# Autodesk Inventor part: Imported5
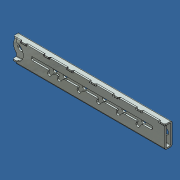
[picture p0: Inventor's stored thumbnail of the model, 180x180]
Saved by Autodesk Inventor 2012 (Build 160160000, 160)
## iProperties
Created: 2016-01
Part Number: Imported5
Material: Steel
Document SubType Name: Modeling
Designer: Admin
Density: 7.85 g/cm^3
Mass: 183.43 g
Surface Area: 256.265 cm^2
Volume: 23.3669 cm^3
Author: Admin
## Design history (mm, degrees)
feature "Base1"
sketch "Sketch1"
  geometry: L1 (147.702, 10.784)-(148.047, 11.276) reference; L2 (147.228, 12.85)-(145.697, 12.85) reference; L3 (138.598, 7.916)-(139.963, 9.865) reference; L4 (134.502, 10.784)-(134.847, 11.276) reference; L5 (134.028, 12.85)-(132.497, 12.85) reference; L6 (125.398, 7.916)-(126.763, 9.865) reference; L7 (121.302, 10.784)-(121.647, 11.276) reference; L8 (120.828, 12.85)-(119.297, 12.85) reference; L9 (112.198, 7.916)-(113.563, 9.865) reference; L10 (108.102, 10.784)-(108.447, 11.276) reference; L11 (107.628, 12.85)-(106.097, 12.85) reference; L12 (98.998, 7.916)-(100.363, 9.865) reference; L13 (94.902, 10.784)-(95.247, 11.276) reference; L14 (94.428, 12.85)-(92.897, 12.85) reference; L15 (85.798, 7.916)-(87.163, 9.865) reference; L16 (81.702, 10.784)-(82.047, 11.276) reference; L17 (81.228, 12.85)-(79.697, 12.85) reference; L18 (72.598, 7.916)-(73.963, 9.865) reference; L19 (68.502, 10.784)-(68.847, 11.276) reference; L20 (68.028, 12.85)-(66.497, 12.85) reference; L21 (59.398, 7.916)-(60.763, 9.865) reference; L22 (55.302, 10.784)-(55.647, 11.276) reference; L23 (54.828, 12.85)-(53.297, 12.85) reference; L24 (46.198, 7.916)-(47.563, 9.865) reference; L25 (42.102, 10.784)-(42.447, 11.276) reference; L26 (22, 12.85)-(41.628, 12.85) reference; L27 (180.75, 17.85)-(22, 17.85) reference; L28 (170.014, 12.85)-(180.75, 12.85) reference; L29 (164.998, 7.916)-(167.557, 11.571) reference; L30 (160.902, 10.784)-(161.247, 11.276) reference; L31 (160.428, 12.85)-(158.897, 12.85) reference; L32 (151.798, 7.916)-(153.163, 9.865) reference; L33 (68.028, 12.85)-(79.697, 12.85); L34 (94.428, 12.85)-(106.097, 12.85); L35 (120.828, 12.85)-(134.028, 12.85); L36 (147.228, 12.85)-(158.897, 12.85); A1 r 2.5 centre (149.75, 9.35) between (147.702, 10.784) and (151.798, 7.916) reference; A2 r 1 centre (147.228, 11.85) between (148.047, 11.276) and (147.228, 12.85) reference; A3 r 7 centre (145.697, 5.85) between (145.697, 12.85) and (139.963, 9.865) reference; A4 r 2.5 centre (136.55, 9.35) between (134.502, 10.784) and (138.598, 7.916) reference; A5 r 1 centre (134.028, 11.85) between (134.847, 11.276) and (134.028, 12.85) reference; A6 r 7 centre (132.497, 5.85) between (132.497, 12.85) and (126.763, 9.865) reference; A7 r 2.5 centre (123.35, 9.35) between (121.302, 10.784) and (125.398, 7.916) reference; A8 r 1 centre (120.828, 11.85) between (121.647, 11.276) and (120.828, 12.85) reference; A9 r 7 centre (119.297, 5.85) between (119.297, 12.85) and (113.563, 9.865) reference; A10 r 2.5 centre (110.15, 9.35) between (108.102, 10.784) and (112.198, 7.916) reference; A11 r 1 centre (107.628, 11.85) between (108.447, 11.276) and (107.628, 12.85) reference; A12 r 7 centre (106.097, 5.85) between (106.097, 12.85) and (100.363, 9.865) reference; A13 r 2.5 centre (96.95, 9.35) between (94.902, 10.784) and (98.998, 7.916) reference; A14 r 1 centre (94.428, 11.85) between (95.247, 11.276) and (94.428, 12.85) reference; A15 r 7 centre (92.897, 5.85) between (92.897, 12.85) and (87.163, 9.865) reference; A16 r 2.5 centre (83.75, 9.35) between (81.702, 10.784) and (85.798, 7.916) reference; A17 r 1 centre (81.228, 11.85) between (82.047, 11.276) and (81.228, 12.85) reference; A18 r 7 centre (79.697, 5.85) between (79.697, 12.85) and (73.963, 9.865) reference; A19 r 2.5 centre (70.55, 9.35) between (68.502, 10.784) and (72.598, 7.916) reference; A20 r 1 centre (68.028, 11.85) between (68.847, 11.276) and (68.028, 12.85) reference; A21 r 7 centre (66.497, 5.85) between (66.497, 12.85) and (60.763, 9.865) reference; A22 r 2.5 centre (57.35, 9.35) between (55.302, 10.784) and (59.398, 7.916) reference; A23 r 1 centre (54.828, 11.85) between (55.647, 11.276) and (54.828, 12.85) reference; A24 r 7 centre (53.297, 5.85) between (53.297, 12.85) and (47.563, 9.865) reference; A25 r 2.5 centre (44.15, 9.35) between (42.102, 10.784) and (46.198, 7.916) reference; A26 r 1 centre (41.628, 11.85) between (42.447, 11.276) and (41.628, 12.85) reference; A27 r 2.5 centre (22, 15.35) between (22, 17.85) and (22, 12.85) reference; A28 r 2.5 centre (180.75, 15.35) between (180.75, 12.85) and (180.75, 17.85) reference; A29 r 3 centre (170.014, 9.85) between (170.014, 12.85) and (167.557, 11.571) reference; A30 r 2.5 centre (162.95, 9.35) between (160.902, 10.784) and (164.998, 7.916) reference; A31 r 1 centre (160.428, 11.85) between (161.247, 11.276) and (160.428, 12.85) reference; A32 r 7 centre (158.897, 5.85) between (158.897, 12.85) and (153.163, 9.865) reference; 1 further point
  constraints: 8 end point, 8 tangent, 4 collinear, 1 point on circle
extrude "reversible fill in 1" join sketch "Sketch1" distance "d0" = 2; taper "d1" = 0 deg
sketch "Sketch2"
  geometry: L1 (130.898, 10.784)-(130.553, 11.276) reference; L2 (125.437, 9.865)-(126.802, 7.916) reference; L3 (118.172, 12.85)-(119.703, 12.85) reference; L4 (104.498, 10.784)-(104.153, 11.276) reference; L5 (99.037, 9.865)-(100.402, 7.916) reference; L6 (78.098, 10.784)-(77.753, 11.276) reference; L7 (72.637, 9.865)-(74.002, 7.916) reference; L8 (51.698, 10.784)-(51.353, 11.276) reference; L9 (46.237, 9.865)-(47.602, 7.916) reference; L10 (131.372, 12.85)-(119.703, 12.85); L11 (104.972, 12.85)-(93.303, 12.85); L12 (91.772, 12.85)-(106.503, 12.85) reference; L13 (78.572, 12.85)-(66.903, 12.85); L14 (65.372, 12.85)-(80.103, 12.85) reference; L15 (52.172, 12.85)-(40.503, 12.85); A1 r 1 centre (131.372, 11.85) between (131.372, 12.85) and (130.553, 11.276) reference; A2 r 2.5 centre (128.85, 9.35) between (126.802, 7.916) and (130.898, 10.784) reference; A3 r 7 centre (119.703, 5.85) between (125.437, 9.865) and (119.703, 12.85) reference; A4 r 1 centre (104.972, 11.85) between (104.972, 12.85) and (104.153, 11.276) reference; A5 r 2.5 centre (102.45, 9.35) between (100.402, 7.916) and (104.498, 10.784) reference; A6 r 7 centre (93.303, 5.85) between (99.037, 9.865) and (93.303, 12.85) reference; A7 r 1 centre (78.572, 11.85) between (78.572, 12.85) and (77.753, 11.276) reference; A8 r 2.5 centre (76.05, 9.35) between (74.002, 7.916) and (78.098, 10.784) reference; A9 r 7 centre (66.903, 5.85) between (72.637, 9.865) and (66.903, 12.85) reference; A10 r 1 centre (52.172, 11.85) between (52.172, 12.85) and (51.353, 11.276) reference; A11 r 2.5 centre (49.65, 9.35) between (47.602, 7.916) and (51.698, 10.784) reference; A12 r 7 centre (40.503, 5.85) between (46.237, 9.865) and (40.503, 12.85) reference; A13 r 7 centre (40.503, 5.85) between (46.237, 9.865) and (40.503, 12.85) reference; A14 r 1 centre (52.172, 11.85) between (52.172, 12.85) and (51.353, 11.276) reference; 1 further point
  constraints: 10 tangent, 8 end point, 2 collinear, 2 parallel
extrude "reversible fill in 2" join sketch "Sketch2" distance "d2" = 2; taper "d3" = 0 deg
body "Solid1"
